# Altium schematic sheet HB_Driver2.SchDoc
size A4
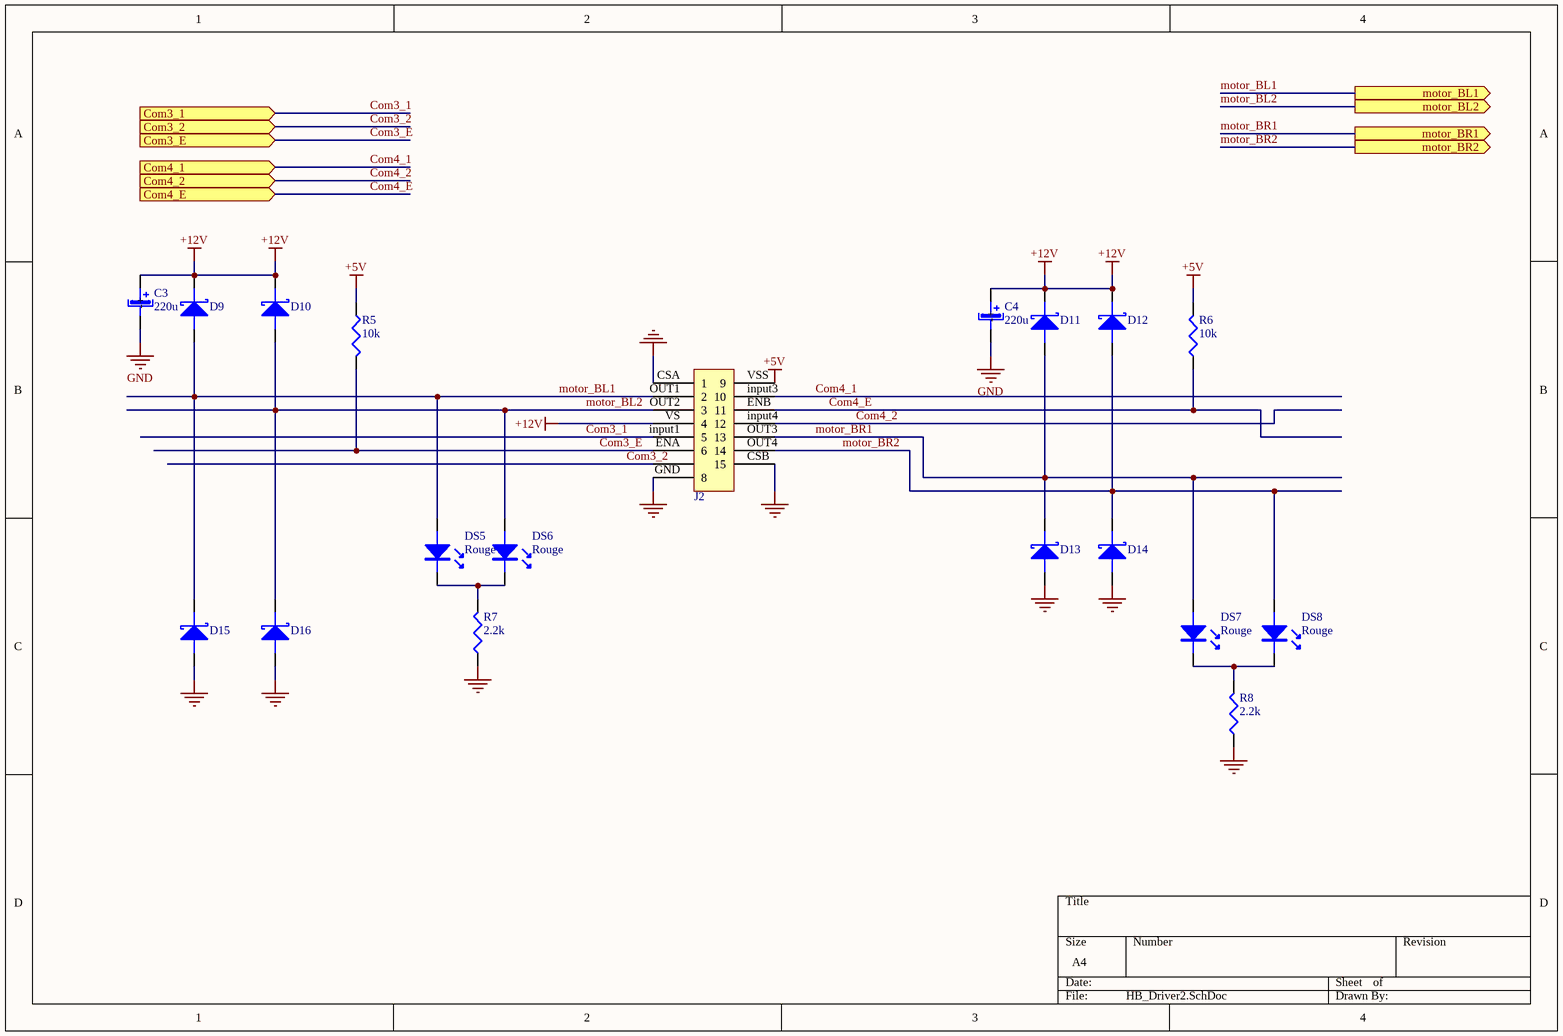
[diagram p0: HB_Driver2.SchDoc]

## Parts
C3  value 220u  [CAPAE0810X700N]  (hidden comment: Cap_220u)
C4  value 220u  [CAPAE0810X700N]  (hidden comment: Cap_220u)
D9  Diode Schottky  [SOD-123]  (value not drawn)
D10  Diode Schottky  [SOD-123]  (value not drawn)
D11  Diode Schottky  [SOD-123]  (value not drawn)
D12  Diode Schottky  [SOD-123]  (value not drawn)
D13  Diode Schottky  [SOD-123]  (value not drawn)
D14  Diode Schottky  [SOD-123]  (value not drawn)
D15  Diode Schottky  [SOD-123]  (value not drawn)
D16  Diode Schottky  [SOD-123]  (value not drawn)
DS5  Color: Rouge  [3.5X2.8X1.9]  (hidden comment: LED)
DS6  Color: Rouge  [3.5X2.8X1.9]  (hidden comment: LED)
DS7  Color: Rouge  [3.5X2.8X1.9]  (hidden comment: LED)
DS8  Color: Rouge  [3.5X2.8X1.9]  (hidden comment: LED)
J2  L298  [MultiWatt15]  (value not drawn)
R5  value 10k  [6-0805_L]  (hidden comment: Res_10k)
R6  value 10k  [6-0805_L]  (hidden comment: Res_10k)
R7  value 2.2k  [6-0805_L]  (hidden comment: Res_2.2k)
R8  value 2.2k  [6-0805_L]  (hidden comment: Res_2.2k)

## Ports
Com3_1 (in), Com3_2 (in), Com3_E (in), Com4_1 (in), Com4_2 (in), Com4_E (in), motor_BL1 (out), motor_BL2 (out), motor_BR1 (out), motor_BR2 (out)

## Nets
+5V: J2.VSS(9) R5.1 R6.2
+12V: C3.POS(+) C4.POS(+) D9.1(K) D10.1(K) D11.1(K) D12.1(K) J2.VS(4)
GND: C3.NEG(-) C4.NEG(-) D13.2(A) D14.2(A) D15.2(A) D16.2(A) J2.CSA(1) J2.CSB(15) J2.GND(8) R7.1 R8.1
Com3_1: J2.input1(5) ; port Com3_1
Com3_2: J2.input2 ; port Com3_2
Com3_E: J2.ENA(6) R5.2 ; port Com3_E
Com4_1: J2.input3(10) ; port Com4_1
Com4_2: J2.input4(12) ; port Com4_2
Com4_E: J2.ENB(11) R6.1 ; port Com4_E
motor_BL1: D9.2(A) D15.1(K) DS5.1(A) J2.OUT1(2) ; port motor_BL1
motor_BL2: D10.2(A) D16.1(K) DS6.1(A) J2.OUT2(3) ; port motor_BL2
motor_BR1: D11.2(A) D13.1(K) DS7.1(A) J2.OUT3(13) ; port motor_BR1
motor_BR2: D12.2(A) D14.1(K) DS8.1(A) J2.OUT4(14) ; port motor_BR2
NetDS5_2: DS5.2(K) DS6.2(K) R7.2
NetDS7_2: DS7.2(K) DS8.2(K) R8.2

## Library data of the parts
C3 C4 = Cap_220u: Condensateur polatisé; Type: Condensateur polarisé debout
J2 = L298: Connecteur
R5 R6 = Res_10k: Résistance standard
R7 R8 = Res_2.2k: Résistance standard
